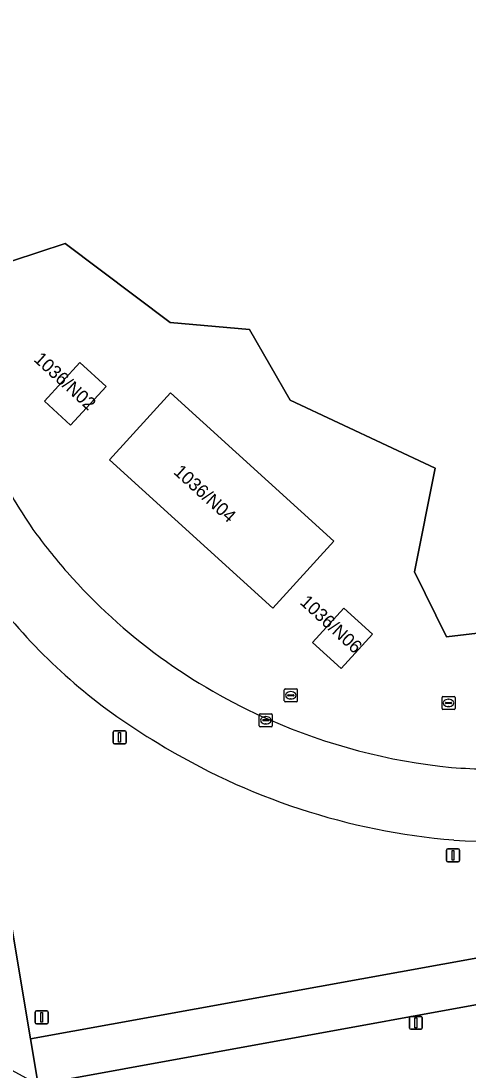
# Model space of a CAD drawing. Extents: x 154324 to 155744, y 382937 to 384188.
# Drawn here: x 155074.4 to 155108.8, y 383487.3 to 383568.1 of the extents above; entities that cross this region are included whole.
import ezdxf

# ---------------------------------------------------------------- set-up
doc = ezdxf.new("R2010")
doc.units = 0
for name, color, linetype in [('IMGEO_Berm_groen', 7, 'Continuous'), ('IMGEO_Fietspad_gesloten', 7, 'Continuous'), ('IMGEO_Groenvoorziening', 7, 'Continuous'), ('IMGEO_Kolk', 7, 'Continuous'), ('IMGEO_Lichtmast', 7, 'Continuous'), ('IMGEO_Loofbos', 7, 'Continuous'), ('IMGEO_Pand', 7, 'Continuous'), ('IMGEO_Pand_nummerreeks', 7, 'Continuous'), ('IMGEO_Rijbaan_regionaal_gesloten', 7, 'Continuous'), ('IMGEO_Rioolput', 7, 'Continuous'), ('IMGEO_Verkeersbordpaal', 7, 'Continuous')]:
    doc.layers.add(name, color=color, linetype=linetype)

msp = doc.modelspace()

# ---------------------------------------------------------------- linework, layer by layer
at = {"layer": 'IMGEO_Berm_groen'}
for points in [[(155070.99, 383520.813), (155071.303, 383519.14), (155070.183, 383519.006), (155075.078, 383489.814), (155129.058, 383499.578), (155131.375, 383500), (155179.798, 383508.805)], [(155180.655, 383505.288), (155151.114, 383500), (155129.466, 383496.092), (155075.664, 383486.308), (155082.147, 383448.215)]]:
    msp.add_lwpolyline(points, dxfattribs=at)
for centre, radius, start, end in [((155107.254, 383550.669), 44.17, 220.30552, 239.49955), ((155111.901, 383556.517), 51.577, 238.34929, 265.28608), ((155111.364, 383556.165), 51.185, 265.85271, 281.38419)]:
    msp.add_arc(centre, radius, start, end, dxfattribs=at)
at = {"layer": 'IMGEO_Fietspad_gesloten'}
msp.add_lwpolyline([(155179.798, 383508.805), (155131.375, 383500), (155129.058, 383499.578), (155075.078, 383489.814), (155075.664, 383486.308), (155129.466, 383496.092), (155151.114, 383500), (155180.655, 383505.288)], close=True, dxfattribs=at)
at = {"layer": 'IMGEO_Groenvoorziening'}
msp.add_lwpolyline([(155127.696, 383641.387), (155155.837, 383565.533), (155150.12, 383546.849), (155147.672, 383535.525), (155141.293, 383537.615), (155133.684, 383529.375), (155124.807, 383520.48), (155115.997, 383521.813), (155107.115, 383520.76), (155104.634, 383525.749), (155106.245, 383533.735), (155095.073, 383538.97), (155091.938, 383544.397), (155085.842, 383544.943), (155077.749, 383551.031), (155073.706, 383549.691), (155069.247, 383557.613), (155064.414, 383584.109), (155059.736, 383616.398), (155060.565, 383620.426)], dxfattribs=at)
for points in [[(155080.902, 383540.005), (155078.176, 383537.029), (155076.153, 383538.881), (155078.878, 383541.857)], [(155098.433, 383528.126), (155093.75, 383522.961), (155081.177, 383534.362), (155085.86, 383539.527)], [(155101.398, 383520.948), (155098.991, 383518.304), (155096.793, 383520.304), (155099.2, 383522.949)]]:
    msp.add_lwpolyline(points, close=True, dxfattribs=at)
for centre, radius, start, end in [((155105.216, 383549.725), 36.405, 205.09321, 214.65877), ((155110.85, 383554.733), 43.897, 215.85343, 221.37304), ((155111.113, 383554.922), 44.218, 221.33167, 246.46956), ((155111.911, 383556.194), 45.705, 246.18851, 264.44742), ((155110.984, 383555.662), 45.094, 265.55431, 272.79585)]:
    msp.add_arc(centre, radius, start, end, dxfattribs=at)
at = {"layer": 'IMGEO_Kolk'}
for p, q in [((155092.697, 383513.907), (155092.697, 383514.759)), ((155092.772, 383514.833), (155093.624, 383514.833)), ((155093.185, 383514.613), (155093.21, 383514.613)), ((155093.698, 383514.759), (155093.698, 383513.907)), ((155093.624, 383513.833), (155092.772, 383513.833)), ((155092.956, 383514.327), (155092.956, 383514.339)), ((155093.394, 383514.29), (155092.996, 383514.29)), ((155092.999, 383514.376), (155093.397, 383514.376)), ((155093.208, 383514.053), (155093.183, 383514.053)), ((155093.44, 383514.339), (155093.44, 383514.327))]:
    msp.add_line(p, q, dxfattribs=at)
for points in [[(155092.697, 383513.907), (155092.697, 383514.759)], [(155092.772, 383514.833), (155093.624, 383514.833)], [(155093.698, 383514.759), (155093.698, 383513.907)], [(155093.624, 383513.833), (155092.772, 383513.833)]]:
    msp.add_lwpolyline(points, dxfattribs=at)
for centre, radius, start, end in [((155092.774, 383514.757), 0.0765, 91.55205, 178.44795), ((155092.774, 383514.757), 0.0765, 91.55205, 178.44795), ((155093.622, 383514.757), 0.0765, 1.55205, 88.44795), ((155093.622, 383514.757), 0.0765, 1.55205, 88.44795), ((155092.774, 383513.909), 0.0765, 181.55205, 268.44795), ((155092.774, 383513.909), 0.0765, 181.55205, 268.44795), ((155092.996, 383514.336), 0.0403, 85.87752, 175.75265), ((155092.993, 383514.326), 0.0366, 178.93798, 274.71019), ((155093.397, 383514.333), 0.043, 264.86636, 352.45326), ((155093.401, 383514.338), 0.0386, 1.73085, 96.63898), ((155093.622, 383513.909), 0.0765, 271.55205, 358.44795), ((155093.622, 383513.909), 0.0765, 271.55205, 358.44795)]:
    msp.add_arc(centre, radius, start, end, dxfattribs=at)
for centre, major_axis, ratio, start_param, end_param in [((155093.184, 383514.333), (-0.387, 0.002), 0.722429, 4.712389, 7.853982), ((155093.209, 383514.333), (-0.39, 0.002), 0.717154, 1.570796, 4.712389)]:
    msp.add_ellipse(centre, major_axis=major_axis, ratio=ratio, start_param=start_param, end_param=end_param, dxfattribs=at)
at = {"layer": 'IMGEO_Lichtmast'}
for p, q in [((155081.449, 383512.612), (155081.449, 383513.412)), ((155081.449, 383513.412), (155081.449, 383512.612)), ((155081.549, 383513.512), (155082.339, 383513.512)), ((155082.339, 383513.512), (155081.549, 383513.512)), ((155082.439, 383513.412), (155082.439, 383512.612)), ((155082.439, 383512.612), (155082.439, 383513.412)), ((155082.339, 383512.512), (155081.549, 383512.512)), ((155081.549, 383512.512), (155082.339, 383512.512)), ((155107.108, 383503.535), (155107.108, 383504.335)), ((155107.108, 383504.335), (155107.108, 383503.535)), ((155107.208, 383504.435), (155107.998, 383504.435)), ((155107.998, 383504.435), (155107.208, 383504.435)), ((155108.098, 383504.335), (155108.098, 383503.535)), ((155108.098, 383503.535), (155108.098, 383504.335)), ((155107.998, 383503.435), (155107.208, 383503.435)), ((155107.208, 383503.435), (155107.998, 383503.435)), ((155104.253, 383490.643), (155104.253, 383491.443)), ((155104.253, 383491.443), (155104.253, 383490.643)), ((155104.353, 383491.543), (155105.143, 383491.543)), ((155105.143, 383491.543), (155104.353, 383491.543)), ((155105.243, 383491.443), (155105.243, 383490.643)), ((155105.243, 383490.643), (155105.243, 383491.443)), ((155105.143, 383490.543), (155104.353, 383490.543)), ((155104.353, 383490.543), (155105.143, 383490.543))]:
    msp.add_line(p, q, dxfattribs=at)
for points in [[(155081.869, 383513.387), (155082.019, 383513.387), (155082.019, 383512.637), (155081.869, 383512.637), (155081.869, 383513.387)], [(155107.528, 383504.31), (155107.678, 383504.31), (155107.678, 383503.56), (155107.528, 383503.56), (155107.528, 383504.31)], [(155104.673, 383491.418), (155104.823, 383491.418), (155104.823, 383490.668), (155104.673, 383490.668), (155104.673, 383491.418)]]:
    msp.add_lwpolyline(points, dxfattribs=at)
for centre, start, end in [((155081.549, 383513.412), 90, 180), ((155081.549, 383513.412), 90, 180), ((155082.339, 383513.412), 0, 90), ((155082.339, 383513.412), 360, 90), ((155081.549, 383512.612), 180, 270), ((155081.549, 383512.612), 180, 270), ((155082.339, 383512.612), 270, 0), ((155082.339, 383512.612), 270, 0), ((155107.208, 383504.335), 90, 180), ((155107.208, 383504.335), 90, 180), ((155107.998, 383504.335), 0, 90), ((155107.998, 383504.335), 360, 90), ((155107.208, 383503.535), 180, 270), ((155107.208, 383503.535), 180, 270), ((155107.998, 383503.535), 270, 0), ((155107.998, 383503.535), 270, 0), ((155104.353, 383491.443), 90, 180), ((155104.353, 383491.443), 90, 180), ((155105.143, 383491.443), 0, 90), ((155105.143, 383491.443), 360, 90), ((155104.353, 383490.643), 180, 270), ((155104.353, 383490.643), 180, 270), ((155105.143, 383490.643), 270, 0), ((155105.143, 383490.643), 270, 0)]:
    msp.add_arc(centre, 0.1, start, end, dxfattribs=at)
at = {"layer": 'IMGEO_Loofbos'}
msp.add_lwpolyline([(155060.565, 383620.426), (155059.736, 383616.398), (155064.414, 383584.109), (155069.247, 383557.613), (155073.706, 383549.691), (155077.749, 383551.031), (155085.842, 383544.943), (155091.938, 383544.397), (155095.073, 383538.97), (155106.245, 383533.735), (155104.634, 383525.749), (155107.115, 383520.76), (155115.997, 383521.813)], dxfattribs=at)
at = {"layer": 'IMGEO_Pand'}
for points in [[(155078.176, 383537.029), (155080.902, 383540.005), (155078.878, 383541.857), (155076.153, 383538.881)], [(155093.75, 383522.961), (155098.433, 383528.126), (155085.86, 383539.527), (155081.177, 383534.362)], [(155098.991, 383518.304), (155101.398, 383520.948), (155099.2, 383522.949), (155096.793, 383520.304)]]:
    msp.add_lwpolyline(points, close=True, dxfattribs=at)
at = {"layer": 'IMGEO_Rijbaan_regionaal_gesloten'}
msp.add_lwpolyline([(155030.623, 383760.14), (155023.592, 383759.163), (155025.319, 383747.582), (155031.523, 383712.699), (155040.998, 383657.511), (155047.66, 383620.638), (155058.726, 383558.566), (155063.68, 383530.41), (155070.593, 383489.047), (155075.664, 383486.308), (155075.078, 383489.814), (155070.183, 383519.006), (155071.303, 383519.14), (155070.99, 383520.813), (155070.622, 383522.809)], dxfattribs=at)
for centre, radius, start, end in [((155105.216, 383549.725), 36.405, 205.09321, 214.65877), ((155110.85, 383554.733), 43.897, 215.85343, 221.37304), ((155111.113, 383554.922), 44.218, 221.33167, 246.46956), ((155107.254, 383550.669), 44.17, 220.30552, 239.49955), ((155111.911, 383556.194), 45.705, 246.18851, 264.44742), ((155111.901, 383556.517), 51.577, 238.34929, 265.28608), ((155110.984, 383555.662), 45.094, 265.55431, 272.79585), ((155111.364, 383556.165), 51.185, 265.85271, 281.38419)]:
    msp.add_arc(centre, radius, start, end, dxfattribs=at)
at = {"layer": 'IMGEO_Rioolput'}
for p, q in [((155094.622, 383515.826), (155094.622, 383516.678)), ((155094.697, 383516.752), (155095.549, 383516.752)), ((155094.881, 383516.246), (155094.881, 383516.258)), ((155095.319, 383516.209), (155094.921, 383516.209)), ((155094.924, 383516.295), (155095.322, 383516.295)), ((155095.11, 383516.532), (155095.135, 383516.532)), ((155095.365, 383516.258), (155095.365, 383516.246)), ((155095.623, 383516.678), (155095.623, 383515.826)), ((155106.834, 383516.166), (155107.686, 383516.166)), ((155095.549, 383515.752), (155094.697, 383515.752)), ((155095.133, 383515.972), (155095.108, 383515.972)), ((155106.759, 383515.24), (155106.759, 383516.092)), ((155107.018, 383515.66), (155107.018, 383515.672)), ((155107.456, 383515.623), (155107.058, 383515.623)), ((155107.061, 383515.709), (155107.459, 383515.709)), ((155107.27, 383515.386), (155107.245, 383515.386)), ((155107.247, 383515.946), (155107.272, 383515.946)), ((155107.502, 383515.672), (155107.502, 383515.66)), ((155107.76, 383516.092), (155107.76, 383515.24)), ((155107.686, 383515.166), (155106.834, 383515.166))]:
    msp.add_line(p, q, dxfattribs=at)
for points in [[(155094.622, 383515.826), (155094.622, 383516.678)], [(155094.697, 383516.752), (155095.549, 383516.752)], [(155095.623, 383516.678), (155095.623, 383515.826)], [(155106.834, 383516.166), (155107.686, 383516.166)], [(155095.549, 383515.752), (155094.697, 383515.752)], [(155106.759, 383515.24), (155106.759, 383516.092)], [(155107.76, 383516.092), (155107.76, 383515.24)], [(155107.686, 383515.166), (155106.834, 383515.166)]]:
    msp.add_lwpolyline(points, dxfattribs=at)
for centre, radius, start, end in [((155094.699, 383516.676), 0.0765, 91.55205, 178.44795), ((155094.699, 383516.676), 0.0765, 91.55205, 178.44795), ((155094.921, 383516.255), 0.0403, 85.87752, 175.75265), ((155094.918, 383516.245), 0.0366, 178.93798, 274.71019), ((155095.322, 383516.252), 0.043, 264.86636, 352.45326), ((155095.326, 383516.257), 0.0386, 1.73085, 96.63898), ((155095.547, 383516.676), 0.0765, 1.55205, 88.44795), ((155095.547, 383516.676), 0.0765, 1.55205, 88.44795), ((155106.836, 383516.09), 0.0765, 91.55205, 178.44795), ((155106.836, 383516.09), 0.0765, 91.55205, 178.44795), ((155107.684, 383516.09), 0.0765, 1.55205, 88.44795), ((155107.684, 383516.09), 0.0765, 1.55205, 88.44795), ((155094.699, 383515.828), 0.0765, 181.55205, 268.44795), ((155094.699, 383515.828), 0.0765, 181.55205, 268.44795), ((155095.547, 383515.828), 0.0765, 271.55205, 358.44795), ((155095.547, 383515.828), 0.0765, 271.55205, 358.44795), ((155107.058, 383515.669), 0.0403, 85.87752, 175.75265), ((155107.055, 383515.659), 0.0366, 178.93798, 274.71019), ((155107.459, 383515.666), 0.043, 264.86636, 352.45326), ((155107.463, 383515.671), 0.0386, 1.73085, 96.63898), ((155106.836, 383515.242), 0.0765, 181.55205, 268.44795), ((155106.836, 383515.242), 0.0765, 181.55205, 268.44795), ((155107.684, 383515.242), 0.0765, 271.55205, 358.44795), ((155107.684, 383515.242), 0.0765, 271.55205, 358.44795)]:
    msp.add_arc(centre, radius, start, end, dxfattribs=at)
for centre, major_axis, ratio, start_param, end_param in [((155095.109, 383516.252), (-0.387, 0.002), 0.722429, 4.712389, 7.853982), ((155095.134, 383516.252), (-0.39, 0.002), 0.717154, 1.570796, 4.712389), ((155107.246, 383515.666), (-0.387, 0.002), 0.722429, 4.712389, 7.853982), ((155107.271, 383515.666), (-0.39, 0.002), 0.717154, 1.570796, 4.712389)]:
    msp.add_ellipse(centre, major_axis=major_axis, ratio=ratio, start_param=start_param, end_param=end_param, dxfattribs=at)
at = {"layer": 'IMGEO_Verkeersbordpaal'}
for p, q in [((155075.55, 383491.97), (155076.34, 383491.97)), ((155076.34, 383491.97), (155075.55, 383491.97)), ((155075.45, 383491.07), (155075.45, 383491.87)), ((155075.45, 383491.87), (155075.45, 383491.07)), ((155076.44, 383491.87), (155076.44, 383491.07)), ((155076.44, 383491.07), (155076.44, 383491.87)), ((155076.34, 383490.97), (155075.55, 383490.97)), ((155075.55, 383490.97), (155076.34, 383490.97))]:
    msp.add_line(p, q, dxfattribs=at)
msp.add_lwpolyline([(155075.87, 383491.845), (155076.02, 383491.845), (155076.02, 383491.095), (155075.87, 383491.095), (155075.87, 383491.845)], dxfattribs=at)
for centre, start, end in [((155075.55, 383491.87), 90, 180), ((155075.55, 383491.87), 90, 180), ((155076.34, 383491.87), 0, 90), ((155076.34, 383491.87), 360, 90), ((155075.55, 383491.07), 180, 270), ((155075.55, 383491.07), 180, 270), ((155076.34, 383491.07), 270, 0), ((155076.34, 383491.07), 270, 0)]:
    msp.add_arc(centre, 0.1, start, end, dxfattribs=at)

# ---------------------------------------------------------------- texts
at = {"layer": 'IMGEO_Pand_nummerreeks'}
for s, rotation, p in [('1036/N02', 317.56593, (155075.27, 383542.026)), ('1036/N04', 317.80186, (155086.033, 383533.361)), ('1036/N06', 317.36321, (155095.762, 383523.331))]:
    msp.add_text(s, height=1, rotation=rotation, dxfattribs=at).set_placement(p)

doc.saveas('drawing.dxf')
